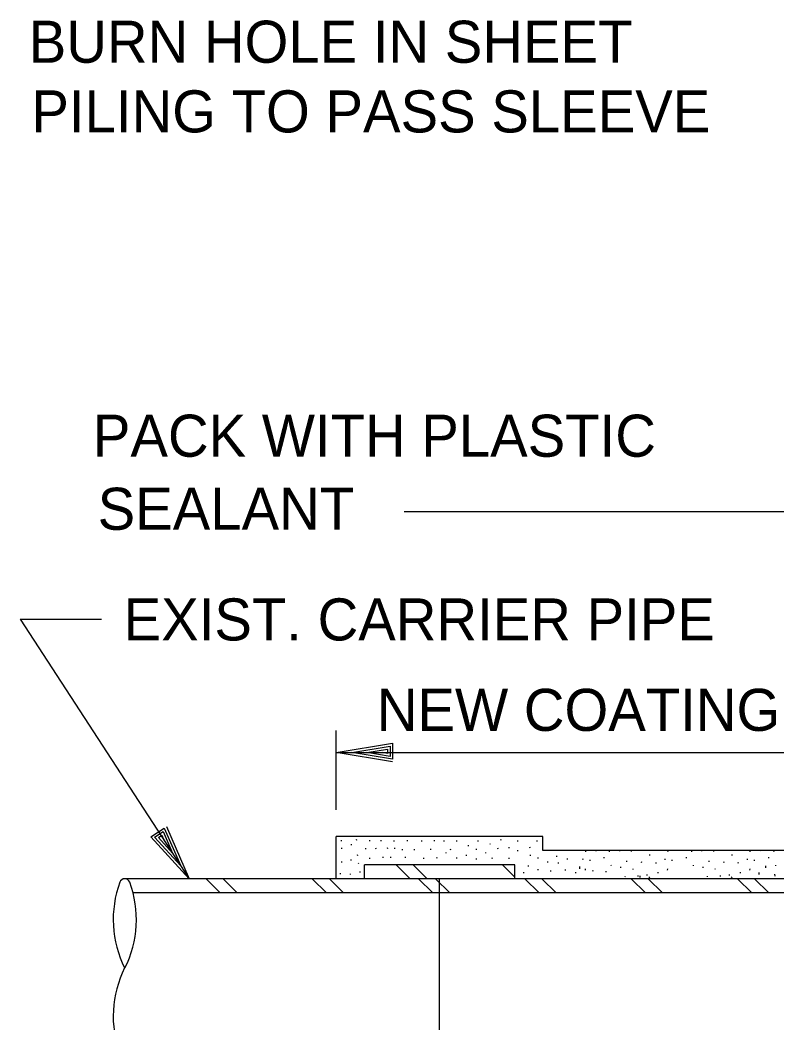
# Model space of a CAD drawing. Extents: x 22411.4 to 22495.4, y 22369.6 to 22415.
# Drawn here: x 22463.731 to 22467.086, y 22388.762 to 22393.211 of the extents above; entities that cross this region are included whole.
import ezdxf

# ---------------------------------------------------------------- set-up
doc = ezdxf.new("R2010")
doc.units = 0
for name, color, linetype in [('Level 1', 7, 'Continuous'), ('Level 2', 7, 'Continuous'), ('Level 4', 7, 'Continuous'), ('Level 8', 7, 'Continuous')]:
    doc.layers.add(name, color=color, linetype=linetype)

msp = doc.modelspace()

# ---------------------------------------------------------------- linework, layer by layer
at = {"layer": 'Level 1'}
for p, q in [((22465.1325, 22389.7079), (22465.1325, 22390.0588)), ((22465.1325, 22389.9614), (22467.3396, 22389.9614)), ((22466.1883, 22389.9614), (22466.1883, 22389.9614)), ((22466.2577, 22389.9614), (22466.2577, 22389.9614))]:
    msp.add_line(p, q, dxfattribs=at)
for points in [[(22465.3818, 22389.92), (22465.1325, 22389.9614), (22465.3818, 22390.0027), (22465.3818, 22389.932), (22465.2018, 22389.9614), (22465.3712, 22389.9894), (22465.3712, 22389.944), (22465.2685, 22389.9614), (22465.3605, 22389.976), (22465.3605, 22389.9574), (22465.3378, 22389.9614)], [(22465.9242, 22389.4094), (22465.8694, 22389.4642)]]:
    msp.add_lwpolyline(points, dxfattribs=at)
for centre, radius, start, end in [((22464.195, 22389.3784), 0.0235, 20.1936, 159.8064), ((22464.6233, 22389.2209), 0.4798, 159.8064, 206.6071), ((22463.7668, 22389.2209), 0.4798, 333.3929, 20.1936), ((22464.6233, 22388.7911), 0.4798, 153.3929, 200.1919)]:
    msp.add_arc(centre, radius, start, end, dxfattribs=at)
at = {"layer": 'Level 2'}
for p, q in [((22465.4343, 22391.0309), (22467.3511, 22391.0309)), ((22463.7306, 22390.5528), (22464.0922, 22390.5528)), ((22463.7306, 22390.5528), (22464.4809, 22389.4017)), ((22466.0492, 22389.5892), (22465.1325, 22389.5892)), ((22465.1325, 22389.4017), (22465.1325, 22389.5892)), ((22466.0492, 22389.5267), (22466.0492, 22389.5892)), ((22466.1883, 22389.5267), (22466.0492, 22389.5267)), ((22472.4933, 22389.5267), (22466.1883, 22389.5267)), ((22469.3408, 22389.5267), (22466.295, 22389.5267)), ((22466.8883, 22389.5047), (22466.888, 22389.5087)), ((22465.2575, 22389.4017), (22465.2575, 22389.4642)), ((22465.9242, 22389.4642), (22465.2575, 22389.4642)), ((22465.9242, 22389.4017), (22465.9242, 22389.4642)), ((22469.3408, 22389.4017), (22464.195, 22389.4017)), ((22465.5908, 22388.61), (22465.5908, 22389.4017)), ((22469.3408, 22389.3392), (22464.2318, 22389.3392))]:
    msp.add_line(p, q, dxfattribs=at)
msp.add_lwpolyline([(22464.3794, 22389.6332), (22464.4809, 22389.4017), (22464.3101, 22389.588), (22464.3693, 22389.6266), (22464.443, 22389.4598), (22464.3271, 22389.5864), (22464.3651, 22389.6111), (22464.4066, 22389.5156), (22464.3441, 22389.5847), (22464.3597, 22389.5949), (22464.3688, 22389.5737)], dxfattribs=at)
at = {"layer": 'Level 8'}
for p, q in [((22465.2232, 22389.5712), (22465.2229, 22389.5753)), ((22465.8633, 22389.5712), (22465.8629, 22389.5753)), ((22465.1556, 22389.569), (22465.1553, 22389.5731)), ((22465.1579, 22389.5352), (22465.1575, 22389.5393)), ((22465.2007, 22389.551), (22465.2004, 22389.555)), ((22465.2638, 22389.5329), (22465.2634, 22389.537)), ((22465.2818, 22389.569), (22465.2815, 22389.5731)), ((22465.3089, 22389.5329), (22465.3085, 22389.537)), ((22465.3314, 22389.569), (22465.3311, 22389.5731)), ((22465.3607, 22389.5352), (22465.3604, 22389.5393)), ((22465.39, 22389.5667), (22465.3897, 22389.5708)), ((22465.3923, 22389.5352), (22465.3919, 22389.5393)), ((22465.4261, 22389.5284), (22465.4257, 22389.5325)), ((22465.4486, 22389.569), (22465.4483, 22389.5731)), ((22465.4801, 22389.5284), (22465.4798, 22389.5325)), ((22465.5117, 22389.5667), (22465.5114, 22389.5708)), ((22465.5523, 22389.5307), (22465.5519, 22389.5347)), ((22465.568, 22389.569), (22465.5677, 22389.5731)), ((22465.6109, 22389.5668), (22465.6105, 22389.5708)), ((22465.6402, 22389.5284), (22465.6398, 22389.5325)), ((22465.6672, 22389.5668), (22465.6669, 22389.5708)), ((22465.719, 22389.5465), (22465.7187, 22389.5505)), ((22465.7551, 22389.5307), (22465.7548, 22389.5347)), ((22465.7619, 22389.5667), (22465.7615, 22389.5708)), ((22465.8159, 22389.5532), (22465.8156, 22389.5573)), ((22465.8498, 22389.5329), (22465.8494, 22389.537)), ((22465.8993, 22389.5374), (22465.899, 22389.5415)), ((22465.9376, 22389.5667), (22465.9373, 22389.5708)), ((22465.9917, 22389.5374), (22465.9914, 22389.5415)), ((22466.0233, 22389.5667), (22466.0229, 22389.5708)), ((22465.1984, 22389.4833), (22465.1981, 22389.4874)), ((22465.2277, 22389.5036), (22465.2274, 22389.5077)), ((22465.2818, 22389.4901), (22465.2815, 22389.4941)), ((22465.3404, 22389.4946), (22465.3401, 22389.4987)), ((22465.3742, 22389.4946), (22465.3739, 22389.4987)), ((22465.4396, 22389.4946), (22465.4393, 22389.4987)), ((22465.5207, 22389.4901), (22465.5204, 22389.4942)), ((22465.5793, 22389.4923), (22465.579, 22389.4964)), ((22465.6199, 22389.5149), (22465.6195, 22389.519)), ((22465.6672, 22389.4923), (22465.6669, 22389.4964)), ((22465.71, 22389.5036), (22465.7097, 22389.5077)), ((22465.7551, 22389.4878), (22465.7548, 22389.4919)), ((22465.7957, 22389.5149), (22465.7953, 22389.519)), ((22465.825, 22389.4901), (22465.8246, 22389.4941)), ((22465.8993, 22389.4901), (22465.899, 22389.4941)), ((22465.9376, 22389.5239), (22465.9373, 22389.528)), ((22465.994, 22389.5036), (22465.9937, 22389.5077)), ((22466.0278, 22389.4923), (22466.0275, 22389.4964)), ((22466.1112, 22389.4991), (22466.1108, 22389.5032)), ((22466.1585, 22389.4878), (22466.1582, 22389.4919)), ((22466.2267, 22389.4857), (22466.2264, 22389.4897)), ((22466.239, 22389.521), (22466.2387, 22389.5251)), ((22466.258, 22389.4816), (22466.2577, 22389.4857)), ((22466.3211, 22389.4938), (22466.3207, 22389.4979)), ((22466.3442, 22389.521), (22466.3438, 22389.5251)), ((22466.442, 22389.5223), (22466.4417, 22389.5264)), ((22466.5236, 22389.5047), (22466.5232, 22389.5087)), ((22466.5915, 22389.4857), (22466.5912, 22389.4897)), ((22466.6037, 22389.521), (22466.6034, 22389.5251)), ((22466.6227, 22389.4816), (22466.6224, 22389.4857)), ((22466.6858, 22389.4938), (22466.6855, 22389.4979)), ((22466.7089, 22389.521), (22466.7086, 22389.5251)), ((22466.8067, 22389.5223), (22466.8064, 22389.5264)), ((22466.9562, 22389.4857), (22466.9559, 22389.4897)), ((22466.9685, 22389.521), (22466.9682, 22389.5251)), ((22466.9875, 22389.4816), (22466.9872, 22389.4857)), ((22467.0506, 22389.4938), (22467.0502, 22389.4979)), ((22467.0737, 22389.521), (22467.0733, 22389.5251)), ((22464.443, 22389.4598), (22464.443, 22389.4598)), ((22465.1579, 22389.4743), (22465.1575, 22389.4784)), ((22465.2322, 22389.4675), (22465.2319, 22389.4716)), ((22465.985, 22389.4562), (22465.9846, 22389.4603)), ((22466.0278, 22389.4405), (22466.0275, 22389.4445)), ((22466.0706, 22389.4743), (22466.0703, 22389.4784)), ((22466.1179, 22389.4698), (22466.1176, 22389.4739)), ((22466.1495, 22389.4382), (22466.1492, 22389.4423)), ((22466.2124, 22389.4458), (22466.2124, 22389.4558)), ((22466.2372, 22389.4406), (22466.2379, 22389.4454)), ((22466.3523, 22389.4585), (22466.352, 22389.4626)), ((22466.3945, 22389.4503), (22466.3942, 22389.4544)), ((22466.4217, 22389.4775), (22466.4213, 22389.4816)), ((22466.4488, 22389.4422), (22466.4485, 22389.4462)), ((22466.4862, 22389.4742), (22466.4881, 22389.4781)), ((22466.5507, 22389.4693), (22466.5504, 22389.4734)), ((22466.6019, 22389.4406), (22466.6027, 22389.4454)), ((22466.7171, 22389.4585), (22466.7167, 22389.4626)), ((22466.7592, 22389.4503), (22466.7589, 22389.4544)), ((22466.7864, 22389.4775), (22466.7861, 22389.4816)), ((22466.8136, 22389.4422), (22466.8132, 22389.4462)), ((22466.851, 22389.4742), (22466.8528, 22389.4781)), ((22466.9155, 22389.4693), (22466.9152, 22389.4734)), ((22466.9667, 22389.4406), (22466.9674, 22389.4454)), ((22467.0377, 22389.4507), (22467.037, 22389.4589)), ((22467.0818, 22389.4585), (22467.0815, 22389.4626)), ((22464.4809, 22389.4017), (22464.4809, 22389.4017)), ((22465.1511, 22389.4224), (22465.1508, 22389.4265)), ((22465.1962, 22389.4202), (22465.1958, 22389.4242)), ((22465.239, 22389.4292), (22465.2387, 22389.4333)), ((22465.9647, 22389.4269), (22465.9644, 22389.431)), ((22466.0841, 22389.4337), (22466.0838, 22389.4378)), ((22466.1955, 22389.4272), (22466.1952, 22389.4313)), ((22466.2712, 22389.4337), (22466.2709, 22389.4378)), ((22466.3298, 22389.4314), (22466.3295, 22389.4355)), ((22466.4142, 22389.4102), (22466.4146, 22389.4138)), ((22466.4719, 22389.4122), (22466.4716, 22389.4163)), ((22466.4806, 22389.4068), (22466.4799, 22389.415)), ((22466.5113, 22389.4163), (22466.511, 22389.4204)), ((22466.5207, 22389.406), (22466.5232, 22389.4102)), ((22466.5602, 22389.4272), (22466.5599, 22389.4313)), ((22466.779, 22389.4102), (22466.7793, 22389.4138)), ((22466.8367, 22389.4122), (22466.8363, 22389.4163)), ((22466.8761, 22389.4163), (22466.8757, 22389.4204)), ((22466.8854, 22389.406), (22466.8879, 22389.4102)), ((22466.925, 22389.4272), (22466.9247, 22389.4313)), ((22467.008, 22389.4211), (22467.0074, 22389.4292)), ((22467.0783, 22389.4134), (22467.0776, 22389.4216))]:
    msp.add_line(p, q, dxfattribs=at)
for points in [[(22466.2849, 22389.5238), (22466.2847, 22389.5267)], [(22466.3895, 22389.5242), (22466.3895, 22389.5267)], [(22466.7542, 22389.5242), (22466.7542, 22389.5267)], [(22467.0144, 22389.5238), (22467.0142, 22389.5267)], [(22465.4605, 22389.4017), (22465.398, 22389.4642)], [(22465.5359, 22389.4017), (22465.4734, 22389.4642)], [(22464.6176, 22389.3392), (22464.5551, 22389.4017)], [(22464.693, 22389.3392), (22464.6305, 22389.4017)], [(22465.089, 22389.3392), (22465.0265, 22389.4017)], [(22465.1644, 22389.3392), (22465.1019, 22389.4017)], [(22465.5604, 22389.3392), (22465.4979, 22389.4017)], [(22465.6358, 22389.3392), (22465.5733, 22389.4017)], [(22466.0318, 22389.3392), (22465.9693, 22389.4017)], [(22466.1072, 22389.3392), (22466.0447, 22389.4017)], [(22466.5032, 22389.3392), (22466.4407, 22389.4017)], [(22466.5786, 22389.3392), (22466.5161, 22389.4017)], [(22466.9746, 22389.3392), (22466.9121, 22389.4017)], [(22467.05, 22389.3392), (22466.9875, 22389.4017)]]:
    msp.add_lwpolyline(points, dxfattribs=at)

# ---------------------------------------------------------------- texts
at = {"layer": 'Level 4'}
for s, height, p in [('BURN HOLE IN SHEET', 0.186667, (22463.769, 22393.0218)), ('PILING TO PASS SLEEVE', 0.186667, (22463.7809, 22392.7128)), ('PACK WITH PLASTIC', 0.186667, (22464.0534, 22391.274)), ('SEALANT', 0.18667, (22464.0746, 22390.9499)), ('EXIST. CARRIER PIPE', 0.186667, (22464.1898, 22390.4589)), ('NEW COATING', 0.186667, (22465.3125, 22390.0577))]:
    msp.add_text(s, height=height, dxfattribs=at).set_placement(p)

doc.saveas('drawing.dxf')
